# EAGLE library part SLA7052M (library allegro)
UNIPOLAR STEPPER-MOTOR TRANSLATOR/PWM DRIVER Source: 97052.pdf
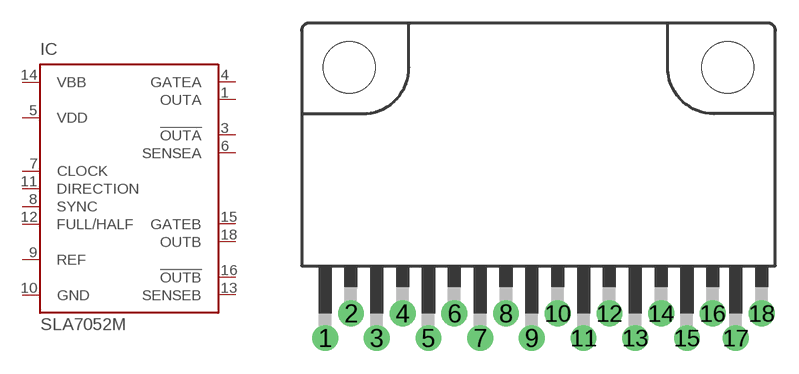
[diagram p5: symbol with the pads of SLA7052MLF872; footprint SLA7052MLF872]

Designator prefix IC

## SLA7052M (MF: ALLEGRO MICROSYSTEMS, INC.; MPN: SLA7052M; OC_FARNELL: unknown; OC_NEWARK: 31K7434)  [SLA7052MLF872]
1  OUTA  out
3  !OUTA  out
4  GATEA  pas
5  VDD  pwr
6  SENSEA  pas
7  CLOCK  pwr
8  SYNC  pwr
9  REF  pwr
10  GND  pwr
11  DIRECTION  pwr
12  FULL/HALF  pwr
13  SENSEB  pas
14  VBB  pwr
15  GATEB  pas
16  !OUTB  out
18  OUTB  out

## Footprint SLA7052MLF872 (pad centres in mm)
SLA7052MLF872 Source: 97052.pdf
drill 1.1 pad 1.676 round: 1 -13.87,-17.6; 2 -12.19,-16; 3 -10.51,-17.6; 4 -8.83,-16; 5 -7.15,-17.6; 6 -5.47,-16; 7 -3.79,-17.6; 8 -2.11,-16; 9 -0.43,-17.6; 10 1.25,-16; 11 2.93,-17.6; 12 4.61,-16; 13 6.29,-17.6; 14 7.97,-16; 15 9.65,-17.6; 16 11.33,-16; 17 12.825,-17.6; 18 14.505,-16
hole 3.35 at -12.3,0
hole 3.35 at 12.3,0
